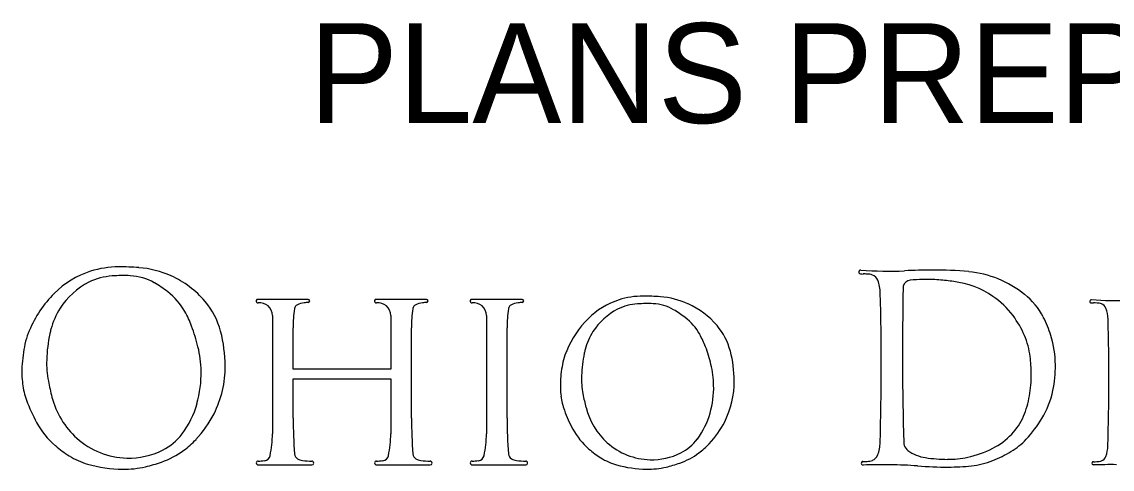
# Model space of a CAD drawing. Extents: x -21.1 to 50.3, y 0 to 22.1.
# Drawn here: x 26.033 to 27.562, y 6.831 to 7.459 of the extents above; entities that cross this region are included whole.
import ezdxf

# ---------------------------------------------------------------- set-up
doc = ezdxf.new("R2010")
doc.units = 0
doc.layers.add('SH_Text', color=7, linetype='Continuous')

msp = doc.modelspace()

# ---------------------------------------------------------------- linework, layer by layer
at = {"layer": 'SH_Text'}
for p, q in [((26.4342, 7.0698), (26.3637, 7.0698)), ((26.6001, 7.0698), (26.5296, 7.0698)), ((26.7342, 7.0698), (26.6637, 7.0698)), ((26.3842, 7.0471), (26.3842, 6.8812)), ((26.5501, 7.0471), (26.5501, 6.9718)), ((26.6842, 7.0471), (26.6842, 6.8812)), ((26.0419, 7.0224), (26.0419, 7.0224)), ((26.4132, 6.9718), (26.4132, 7.0298)), ((26.5791, 6.9029), (26.5791, 7.0298)), ((26.7132, 6.9029), (26.7132, 7.0298)), ((26.7955, 6.9948), (26.7955, 6.9948)), ((26.5501, 6.9718), (26.4132, 6.9718)), ((26.4132, 6.9029), (26.4132, 6.9582)), ((26.4132, 6.9582), (26.5501, 6.9582)), ((26.5501, 6.9582), (26.5501, 6.8812)), ((26.3641, 6.8375), (26.4394, 6.8375)), ((26.53, 6.8375), (26.6053, 6.8375)), ((26.6641, 6.8375), (26.7393, 6.8375))]:
    msp.add_line(p, q, dxfattribs=at)
for centre, radius, start, end in [((26.1667, 6.9907), 0.1244, 107.613, 135.2994), ((26.1688, 6.9841), 0.1313, 90.0889, 107.613), ((26.1692, 6.7512), 0.3642, 85.6243, 90.0889), ((26.1866, 6.9797), 0.135, 65.7405, 85.6243), ((27.2088, 7.1083), 0.00269, 85.6429, 267.986), ((27.2482, 7.6243), 0.5149, 265.6429, 272.4818), ((27.323, 5.8988), 1.2123, 90.6415, 92.4818), ((27.3146, 6.6472), 0.4638, 84.3199, 90.6415), ((27.3458, 6.9609), 0.1485, 51.3332, 84.3199), ((26.1728, 7.0023), 0.1024, 116.7026, 147.5385), ((26.1647, 7.0183), 0.0845, 93.5922, 116.7026), ((26.1749, 6.8563), 0.2469, 87.6816, 93.5922), ((26.1819, 7.03), 0.0729, 59.809, 87.6816), ((26.1865, 6.9793), 0.1355, 40.354, 65.7405), ((27.2132, 7.2314), 0.126, 267.986, 269.6056), ((27.211, 6.9152), 0.1903, 87.8585, 89.6056), ((27.2171, 7.0797), 0.0257, 70.7604, 87.8585), ((27.2216, 7.0926), 0.012, 19.7623, 70.7604), ((27.1784, 7.077), 0.058, 1.7776, 19.7623), ((27.279, 7.0861), 0.0106, 94.329, 166.7992), ((27.3097, 6.6813), 0.4166, 91.9186, 94.329), ((27.302, 6.9107), 0.1871, 84.8974, 91.9186), ((27.2667, 6.5152), 0.5842, 82.8496, 84.8974), ((27.3239, 6.9714), 0.1244, 55.5454, 82.8496), ((26.1964, 6.9614), 0.1661, 135.2994, 157.2066), ((26.1342, 6.9479), 0.1679, 52.0865, 59.809), ((26.1791, 7.0057), 0.0948, 29.7562, 52.0865), ((23.7479, 6.9773), 3.4899, 358.2224, 1.6678), ((31.7614, 6.9971), 4.4939, 178.862, 181.6334), ((27.279, 7.0861), 0.0106, 166.7992, 178.862), ((26.2093, 6.9987), 0.1055, 14.436, 40.354), ((26.3637, 7.0673), 0.00249, 90, 277.32), ((26.3663, 7.0471), 0.0179, 0, 97.32), ((26.4316, 7.0354), 0.0297, 95.8947, 114.8736), ((26.4505, 6.8527), 0.2134, 94.3316, 95.8947), ((26.4342, 7.0676), 0.0022, 274.3316, 90), ((26.5296, 7.0673), 0.00249, 90, 277.32), ((26.5322, 7.0471), 0.0179, 0, 97.32), ((26.5975, 7.0354), 0.0297, 95.8947, 114.8736), ((26.6164, 6.8527), 0.2134, 94.3316, 95.8947), ((26.6001, 7.0676), 0.0022, 274.3316, 90), ((26.6637, 7.0673), 0.00249, 90, 277.32), ((26.6663, 7.0471), 0.0179, 0, 97.32), ((26.7316, 7.0354), 0.0297, 95.8947, 114.8736), ((26.7505, 6.8527), 0.2134, 94.3316, 95.8947), ((26.7342, 7.0676), 0.0022, 274.3316, 90), ((26.9023, 6.9677), 0.1064, 107.613, 135.2994), ((26.9006, 6.9913), 0.0723, 93.5922, 116.7026), ((26.9041, 6.9621), 0.1123, 90.0889, 107.613), ((26.9093, 6.8527), 0.2112, 87.6816, 93.5922), ((26.9044, 6.7628), 0.3116, 85.6243, 90.0889), ((26.9153, 7.0013), 0.0624, 59.809, 87.6816), ((26.9193, 6.9583), 0.1155, 65.7405, 85.6243), ((26.9192, 6.9579), 0.1159, 40.354, 65.7405), ((27.3267, 6.9755), 0.1195, 36.7351, 55.5454), ((27.3757, 6.9983), 0.1007, 27.6817, 51.3332), ((27.5324, 7.0671), 0.00228, 85.6429, 267.986), ((27.5361, 7.1715), 0.1067, 267.986, 269.6056), ((27.5657, 7.5045), 0.4363, 265.6429, 272.4818), ((27.5342, 6.9036), 0.1612, 87.8585, 89.6056), ((27.5394, 7.043), 0.0217, 70.7604, 87.8585), ((27.5432, 7.0539), 0.0102, 19.7623, 70.7604), ((26.1728, 7.0023), 0.1024, 147.5385, 165.5071), ((26.1426, 6.9848), 0.1368, 20.2973, 29.7562), ((26.6082, 7.0298), 0.195, 172.0456, 180), ((26.4222, 7.0558), 0.00718, 114.8736, 172.0456), ((26.7741, 7.0298), 0.195, 172.0456, 180), ((26.5881, 7.0558), 0.00718, 114.8736, 172.0456), ((26.9081, 7.0298), 0.195, 172.0456, 180), ((26.7222, 7.0558), 0.00718, 114.8736, 172.0456), ((26.9075, 6.9776), 0.0876, 116.7026, 147.5385), ((26.8744, 6.9311), 0.1436, 52.0865, 59.809), ((27.5066, 7.0407), 0.0491, 1.7776, 19.7623), ((26.0229, 6.9405), 0.2644, 13.7527, 20.2973), ((26.9277, 6.9426), 0.1421, 135.2994, 157.2066), ((26.9129, 6.9805), 0.0811, 29.7562, 52.0865), ((26.9387, 6.9745), 0.0903, 14.436, 40.354), ((27.3111, 6.9638), 0.139, 23.505, 36.7351), ((27.3296, 6.9741), 0.1527, 17.0568, 27.6817), ((24.5995, 6.9561), 2.9574, 358.2224, 1.6678), ((26.1332, 6.9863), 0.0982, 158.442, 167.8164), ((26.1964, 6.9614), 0.1661, 157.2066, 158.442), ((26.2715, 6.9789), 0.2039, 167.8795, 178.2857), ((26.2239, 6.9891), 0.1552, 165.5071, 167.8795), ((26.1138, 6.9741), 0.2042, 0.6253, 14.436), ((26.9075, 6.9776), 0.0876, 147.5385, 165.5071), ((26.8816, 6.9626), 0.117, 20.2973, 29.7562), ((27.3426, 6.9775), 0.1045, 6.7275, 23.505), ((27.3396, 6.9772), 0.1423, 0.2266, 17.0568), ((26.2344, 6.9645), 0.2017, 167.8164, 176.8679), ((26.1266, 6.9659), 0.1577, 1.1426, 13.7527), ((26.7793, 6.9248), 0.2262, 13.7527, 20.2973), ((26.8736, 6.9639), 0.084, 158.442, 167.8164), ((26.9277, 6.9426), 0.1421, 157.2066, 158.442), ((26.9919, 6.9575), 0.1744, 167.8795, 178.2857), ((26.9512, 6.9663), 0.1328, 165.5071, 167.8795), ((26.857, 6.9535), 0.1747, 0.6253, 14.436), ((27.2152, 6.9625), 0.2329, 0.6041, 6.7275), ((26.1637, 6.9684), 0.1309, 176.8679, 187.4835), ((26.208, 6.9807), 0.1404, 178.2857, 190.5998), ((26.173, 6.9748), 0.1449, 333.1433, 0.6253), ((26.9602, 6.9453), 0.1726, 167.8164, 176.8679), ((26.8679, 6.9465), 0.1349, 1.1426, 13.7527), ((27.3036, 6.977), 0.1783, 348.6268, 0.2266), ((26.1273, 6.9659), 0.1569, 344.2873, 1.1426), ((26.9376, 6.9592), 0.1201, 178.2857, 190.5998), ((27.2825, 6.9632), 0.1656, 349.9228, 0.6041), ((26.1461, 6.9661), 0.1132, 187.4835, 199.5864), ((26.4011, 7.0169), 0.3368, 190.5998, 194.5022), ((26.8997, 6.9486), 0.1119, 176.8679, 187.4835), ((26.8686, 6.9465), 0.1342, 344.2873, 1.1426), ((26.9076, 6.9541), 0.124, 333.1433, 0.6253), ((27.358, 6.9661), 0.1227, 328.8631, 348.6268), ((26.2428, 7.0005), 0.2158, 199.5864, 208.6065), ((26.1885, 6.9619), 0.1172, 194.5022, 227.8932), ((26.8847, 6.9466), 0.0968, 187.4835, 199.5864), ((27.1028, 6.9901), 0.2882, 190.5998, 194.5022), ((27.312, 6.958), 0.1356, 337.2804, 349.9228), ((26.1534, 6.9586), 0.1299, 323.2967, 344.2873), ((26.9674, 6.976), 0.1846, 199.5864, 208.6065), ((26.9209, 6.943), 0.1003, 194.5022, 227.8932), ((26.8909, 6.9402), 0.1111, 323.2967, 344.2873), ((26.1559, 6.953), 0.1168, 208.6065, 229.3453), ((26.1644, 6.9791), 0.1546, 316.7511, 333.1433), ((27.057, 6.9029), 0.6438, 180, 184.4616), ((27.2229, 6.9029), 0.6438, 180, 184.4616), ((27.357, 6.9029), 0.6438, 180, 184.4616), ((26.9003, 6.9578), 0.1322, 316.7511, 333.1433), ((27.3617, 6.9372), 0.0817, 316.2141, 337.2804), ((27.3151, 6.992), 0.1729, 316.6969, 328.8631), ((26.1962, 6.9266), 0.0764, 296.3448, 323.2967), ((26.2401, 6.8812), 0.1441, 347.6428, 360), ((26.406, 6.8812), 0.1441, 347.6428, 360), ((26.5401, 6.8812), 0.1441, 347.6428, 360), ((26.893, 6.9355), 0.0999, 208.6065, 229.3453), ((27.3482, 6.9501), 0.1004, 297.1175, 316.2141), ((26.1872, 6.9895), 0.1648, 229.3453, 237.7571), ((26.1825, 6.9552), 0.1082, 227.8932, 268.7516), ((26.1854, 6.9594), 0.1258, 306.2827, 316.7511), ((26.9157, 6.9373), 0.0926, 227.8932, 268.7516), ((26.9275, 6.9129), 0.0654, 296.3448, 323.2967), ((26.9182, 6.9409), 0.1076, 306.2827, 316.7511), ((27.1782, 6.8708), 0.058, 340.2377, 358.2224), ((27.2838, 6.8694), 0.0145, 181.6334, 198.7573), ((27.2838, 6.8694), 0.0145, 198.7573, 233.0825), ((27.3676, 6.9425), 0.1007, 301.0688, 316.6969), ((27.5064, 6.8659), 0.0491, 340.2377, 358.2224), ((26.1517, 6.9332), 0.0983, 237.7571, 254.2366), ((26.1824, 6.9545), 0.1075, 268.7516, 296.3448), ((26.1882, 6.9555), 0.121, 289.5494, 306.2827), ((26.3721, 6.8523), 0.00897, 275.8469, 347.6428), ((26.4238, 6.8535), 0.00863, 184.4616, 238.9441), ((26.538, 6.8523), 0.00897, 275.8469, 347.6428), ((26.5897, 6.8535), 0.00863, 184.4616, 238.9441), ((26.6721, 6.8523), 0.00897, 275.8469, 347.6428), ((26.7237, 6.8535), 0.00863, 184.4616, 238.9441), ((26.9198, 6.9666), 0.141, 229.3453, 237.7571), ((26.9157, 6.9367), 0.092, 268.7516, 296.3448), ((26.9207, 6.9376), 0.1035, 289.5494, 306.2827), ((27.2214, 6.8553), 0.012, 289.2396, 340.2377), ((27.3072, 6.9005), 0.0534, 233.0825, 262.024), ((27.3278, 6.99), 0.1452, 282.4077, 297.1175), ((27.3258, 7.0119), 0.1817, 292.086, 301.0688), ((27.5431, 6.8528), 0.0102, 289.2396, 340.2377), ((26.1773, 7.0239), 0.1925, 254.2366, 269.1033), ((26.1763, 6.9611), 0.1297, 269.1033, 283.3048), ((26.1565, 7.0449), 0.2159, 283.3048, 289.5494), ((26.3641, 6.8402), 0.00264, 91.3892, 270), ((26.3613, 6.9581), 0.1153, 271.3892, 275.8469), ((26.4283, 6.861), 0.0174, 238.9441, 264.1674), ((26.4479, 7.0529), 0.2103, 264.1674, 267.7015), ((26.4394, 6.8401), 0.00262, 270, 87.7015), ((26.53, 6.8402), 0.00264, 91.3892, 270), ((26.5272, 6.9581), 0.1153, 271.3892, 275.8469), ((26.5942, 6.861), 0.0174, 238.9441, 264.1674), ((26.6138, 7.0529), 0.2103, 264.1674, 267.7015), ((26.6053, 6.8401), 0.00262, 270, 87.7015), ((26.6641, 6.8402), 0.00264, 91.3892, 270), ((26.6613, 6.9581), 0.1153, 271.3892, 275.8469), ((26.7283, 6.861), 0.0174, 238.9441, 264.1674), ((26.7479, 7.0529), 0.2103, 264.1674, 267.7015), ((26.7393, 6.8401), 0.00262, 270, 87.7015), ((26.8894, 6.9185), 0.0841, 237.7571, 254.2366), ((26.9113, 6.9961), 0.1647, 254.2366, 269.1033), ((26.9105, 6.9424), 0.111, 269.1033, 283.3048), ((26.8935, 7.0141), 0.1847, 283.3048, 289.5494), ((27.2121, 6.8398), 0.00256, 90.3944, 271.2938), ((27.2108, 7.0326), 0.1903, 270.3944, 272.1415), ((27.2423, 5.5021), 1.3355, 89.661, 91.2938), ((27.2169, 6.8681), 0.0257, 272.1415, 289.2396), ((27.247, 6.2933), 0.5443, 85.604, 89.661), ((27.3302, 7.376), 0.5416, 265.604, 270.141), ((27.3345, 7.0953), 0.2501, 262.024, 269.0831), ((27.3325, 6.9686), 0.1233, 269.0831, 282.4077), ((27.3308, 7.1651), 0.3307, 270.141, 275.8096), ((27.3532, 6.9444), 0.1088, 275.8096, 292.086), ((27.5352, 6.8397), 0.00217, 90.3944, 271.2943), ((27.5341, 7.0031), 0.1612, 270.3944, 272.1415), ((27.5608, 5.7061), 1.1317, 89.661, 91.2938), ((27.5393, 6.8637), 0.0217, 272.1415, 289.2396)]:
    msp.add_arc(centre, radius, start, end, dxfattribs=at)

# ---------------------------------------------------------------- texts
msp.add_text('PLANS PREPARED BY:', height=0.14, dxfattribs=at).set_placement((26.4355, 7.3174))

doc.saveas('drawing.dxf')
